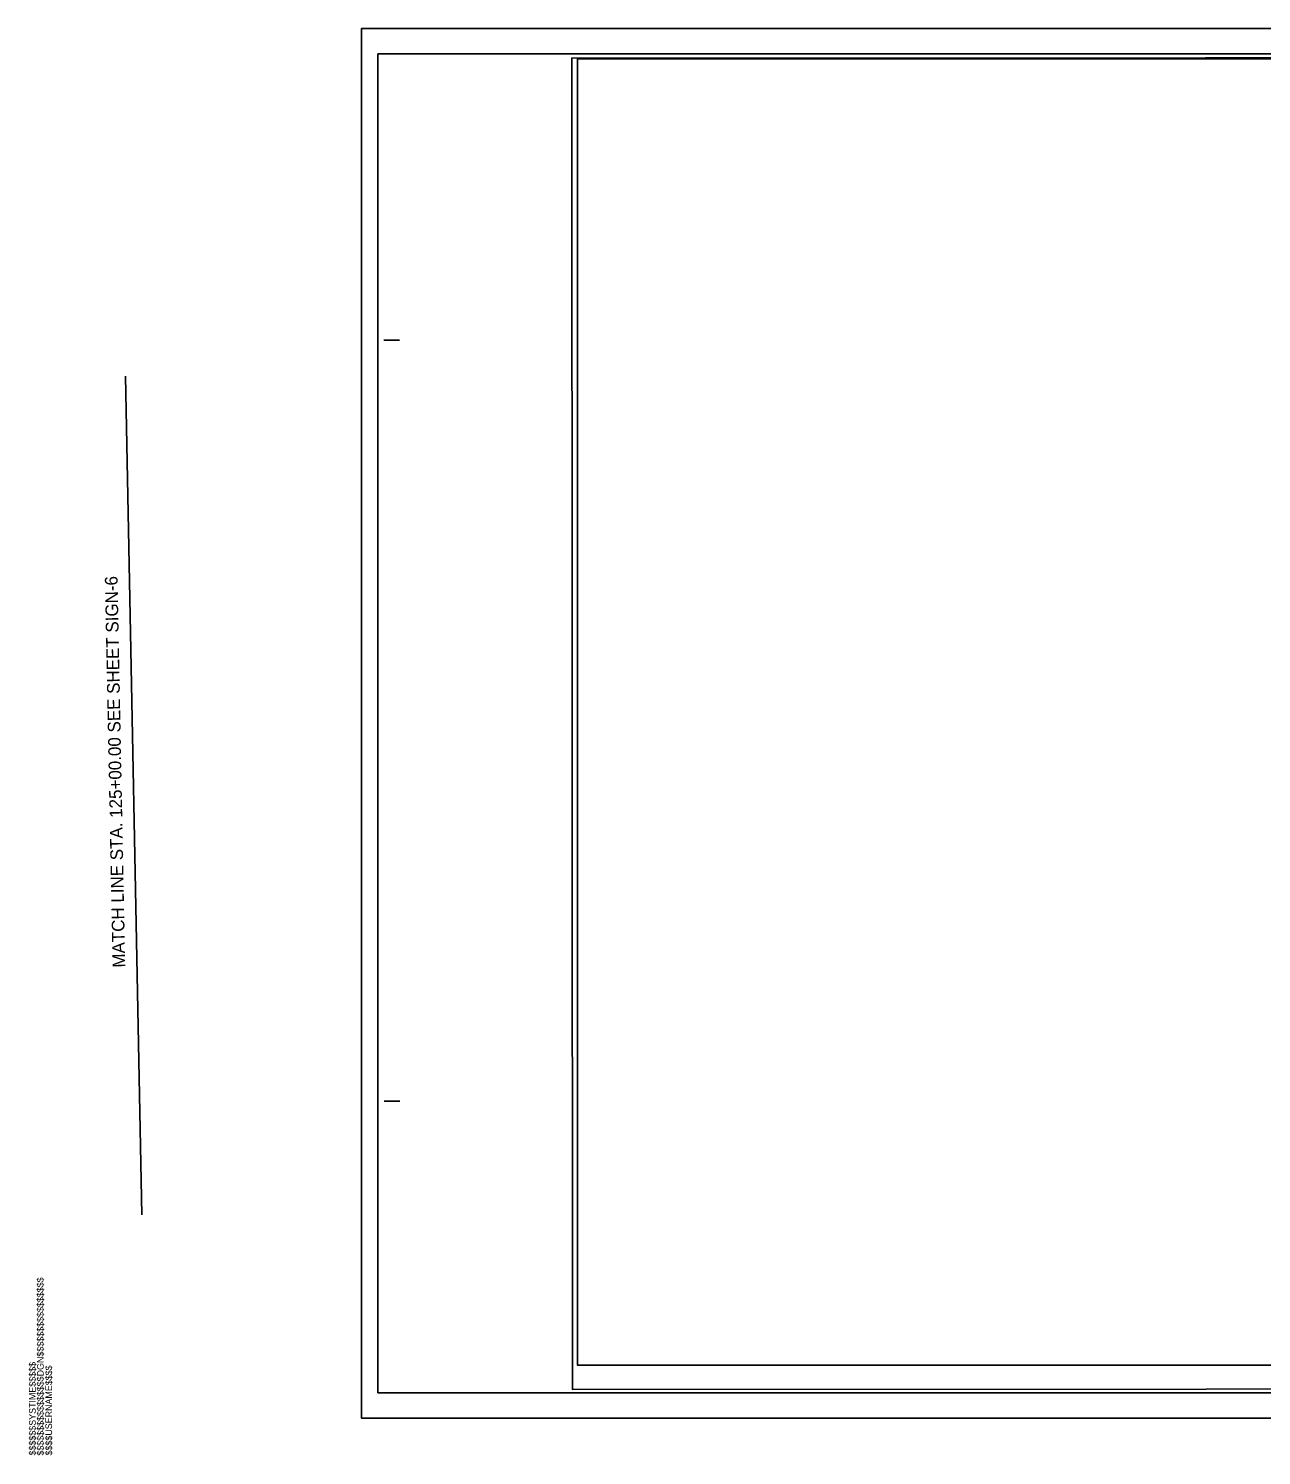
# Model space of a CAD drawing. Extents: x 1721764 to 1725755, y 971408 to 972569.
# Drawn here: x 1721764 to 1722736, y 971423 to 972548 of the extents above; entities that cross this region are included whole.
import ezdxf

# ---------------------------------------------------------------- set-up
doc = ezdxf.new("R2010")
doc.units = 0
for name, color, linetype in [('Matchline', 7, 'Continuous'), ('Matchline Text', 7, 'Continuous'), ('Prop Text', 7, 'Continuous'), ('Scratch_Level_3', 7, 'Continuous'), ('Sheet Plan CELL', 7, 'Continuous'), ('Sheet Plan Layout CELL', 7, 'Continuous'), ('Sheet Plot Border Inside CELL', 7, 'Continuous'), ('Sheet Plot Border Outside CELL', 7, 'Continuous')]:
    doc.layers.add(name, color=color, linetype=linetype)

msp = doc.modelspace()

# ---------------------------------------------------------------- linework, layer by layer
at = {"layer": 'Matchline'}
msp.add_line((1721853, 971612.6), (1721839.9, 972273.8), dxfattribs=at)
msp.add_line((1721853, 971612.6), (1721839.9, 972273.8), dxfattribs=at)
at = {"layer": 'Scratch_Level_3'}
msp.add_lwpolyline([(1722196.6, 972524), (1723476.5, 972524), (1723476.5, 972306.2), (1723676.6, 972306.2), (1723676.6, 971548.6), (1723348.6, 971548.6), (1723348.6, 971494), (1722196.6, 971494)], close=True, dxfattribs=at)
at = {"layer": 'Sheet Plan CELL'}
for p, q in [((1722039.1, 971472.3), (1722039.1, 971472.3)), ((1722026.1, 971452.3), (1722026.1, 971452.3))]:
    msp.add_line(p, q, dxfattribs=at)
at = {"layer": 'Sheet Plan Layout CELL'}
msp.add_lwpolyline([(1723691.7, 972525.5), (1722192, 972524.7), (1722192.6, 971474.9), (1723692.3, 971475.7)], close=True, dxfattribs=at)
at = {"layer": 'Sheet Plot Border Inside CELL'}
for p, q in [((1722043.7, 972302.2), (1722056.2, 972302.2)), ((1722044, 971702.3), (1722056.5, 971702.3))]:
    msp.add_line(p, q, dxfattribs=at)
msp.add_lwpolyline([(1723704.2, 972528), (1722039.1, 972528), (1722039.1, 971472.3), (1723704.2, 971472.3)], close=True, dxfattribs=at)
at = {"layer": 'Sheet Plot Border Outside CELL'}
msp.add_lwpolyline([(1723708.7, 972548), (1722026.1, 972548), (1722026.1, 971452.3), (1723708.7, 971452.3)], close=True, dxfattribs=at)

# ---------------------------------------------------------------- texts
at = {"layer": 'Matchline Text'}
msp.add_text('MATCH LINE STA. 125+00.00 SEE SHEET SIGN-6', height=10, rotation=91.1317, dxfattribs=at).set_placement((1721839.8, 971807.6))
at = {"layer": 'Prop Text'}
for s, p in [('$$$$$$$$$$$$$$$$DGN$$$$$$$$$$$$$$$$', (1721775.5, 971422.7)), ('$$$$$$SYSTIME$$$$$', (1721769.2, 971422.8)), ('$$$$USERNAME$$$$', (1721782.1, 971422.8))]:
    msp.add_text(s, height=5.249, rotation=90.0308, dxfattribs=at).set_placement(p)

doc.saveas('drawing.dxf')
